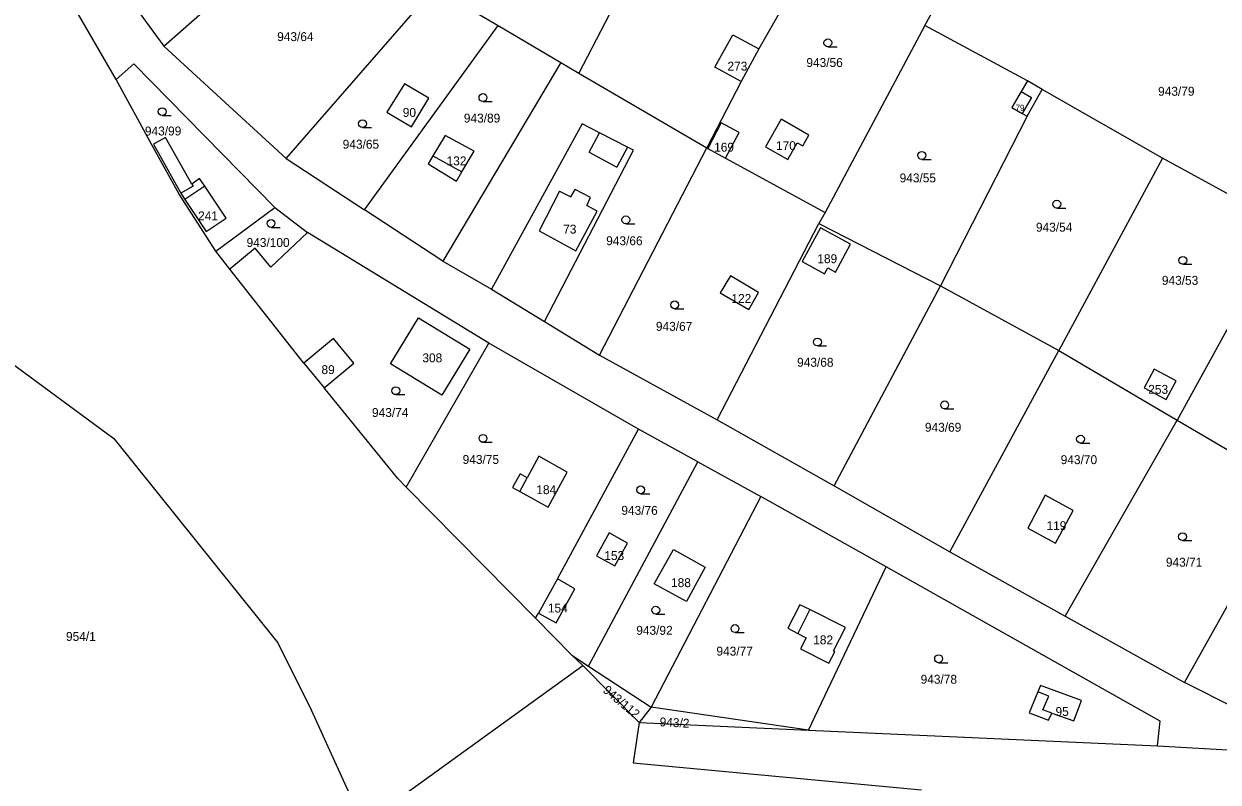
# Model space of a CAD drawing. Extents: x -751333 to -746055, y -1133395 to -1129777.
# Drawn here: x -751034.6 to -750806.6, y -1131231.7 to -1131087 of the extents above; entities that cross this region are included whole.
import ezdxf

# ---------------------------------------------------------------- set-up
doc = ezdxf.new("R2010")
doc.units = 0
for name, color, linetype in [('Hranice parcel', 7, 'Continuous'), ('Parcelní čísla', 7, 'Continuous'), ('Vnitřní kresba', 7, 'Continuous'), ('Značky kultur', 7, 'Continuous')]:
    doc.layers.add(name, color=color, linetype=linetype)

msp = doc.modelspace()

# ---------------------------------------------------------------- linework, layer by layer
at = {"layer": 'Hranice parcel'}
for p, q in [((-751017.03, -1131097.62), (-751052.97, -1131035.02)), ((-750908.02, -1131056.72), (-750928.66, -1131096.41)), ((-751028.03, -1131063.75), (-751007.91, -1131091.26)), ((-751007.91, -1131091.26), (-750978.69, -1131065.52)), ((-750882.26, -1131070.62), (-750894.32, -1131091.73)), ((-750984.53, -1131112.67), (-750956.17, -1131080.13)), ((-750954.6, -1131081.11), (-750944.07, -1131087.29)), ((-750969.58, -1131122.47), (-750944.07, -1131087.29)), ((-750944.07, -1131087.29), (-750932.1, -1131094.36)), ((-750902.67, -1131095.24), (-750899.29, -1131089.06)), ((-750899.29, -1131089.06), (-750894.32, -1131091.73)), ((-750862.62, -1131087.31), (-750881.63, -1131122.97)), ((-750843.03, -1131097.87), (-750862.62, -1131087.31)), ((-751007.91, -1131091.26), (-750984.53, -1131112.67)), ((-750894.32, -1131091.73), (-750897.66, -1131097.98)), ((-750932.1, -1131094.36), (-750954.62, -1131132.27)), ((-750932.1, -1131094.36), (-750928.66, -1131096.41)), ((-750897.66, -1131097.98), (-750902.67, -1131095.24)), ((-750928.66, -1131096.41), (-750904.23, -1131110.65)), ((-750897.66, -1131097.98), (-750904.23, -1131110.65)), ((-750843.03, -1131097.87), (-750844.23, -1131099.89)), ((-750840.17, -1131099.52), (-750843.03, -1131097.87)), ((-750843.07, -1131104.63), (-750840.17, -1131099.52)), ((-750817.2, -1131112.65), (-750840.17, -1131099.52)), ((-750843.07, -1131104.63), (-750859.59, -1131136.99)), ((-750844.01, -1131104.1), (-750843.07, -1131104.63)), ((-750928.04, -1131106.09), (-750945.33, -1131137.63)), ((-750935.22, -1131143.83), (-750918.22, -1131111.09)), ((-750924.73, -1131150.26), (-750904.23, -1131110.65)), ((-750904.23, -1131110.65), (-750904.04, -1131110.76)), ((-750904.04, -1131110.76), (-750900.68, -1131112.63)), ((-750984.53, -1131112.67), (-750969.58, -1131122.47)), ((-750900.68, -1131112.63), (-750881.63, -1131122.97)), ((-750817.2, -1131112.65), (-750837.03, -1131149.34)), ((-750793.96, -1131125.37), (-750817.2, -1131112.65)), ((-750997.95, -1131130.36), (-750986.72, -1131122.03)), ((-750986.72, -1131122.03), (-750980.47, -1131126.84)), ((-750954.62, -1131132.27), (-750969.58, -1131122.47)), ((-750881.63, -1131122.97), (-750882.81, -1131125.12)), ((-750902.26, -1131162.57), (-750882.81, -1131125.12)), ((-750882.81, -1131125.12), (-750859.59, -1131136.99)), ((-750793.96, -1131125.37), (-750814.41, -1131162.65)), ((-750980.47, -1131126.84), (-750987.49, -1131133.44)), ((-750945.82, -1131147.97), (-750980.47, -1131126.84)), ((-750995.3, -1131133.81), (-750997.95, -1131130.36)), ((-750954.62, -1131132.27), (-750945.33, -1131137.63)), ((-750981.17, -1131151.77), (-750995.3, -1131133.81)), ((-750879.9, -1131175.15), (-750859.59, -1131136.99)), ((-750859.59, -1131136.99), (-750837.03, -1131149.34)), ((-750945.33, -1131137.63), (-750935.22, -1131143.83)), ((-750935.22, -1131143.83), (-750924.73, -1131150.26)), ((-750975.52, -1131147.07), (-750981.17, -1131151.77)), ((-750971.63, -1131151.75), (-750975.52, -1131147.07)), ((-750961.63, -1131175.41), (-750945.82, -1131147.97)), ((-750917.27, -1131164.38), (-750945.82, -1131147.97)), ((-750924.73, -1131150.26), (-750902.26, -1131162.57)), ((-750857.83, -1131187.77), (-750837.03, -1131149.34)), ((-750837.03, -1131149.34), (-750814.41, -1131162.65)), ((-750981.17, -1131151.77), (-750977.28, -1131156.45)), ((-750977.28, -1131156.45), (-750971.63, -1131151.75)), ((-750932.76, -1131192.95), (-750917.27, -1131164.38)), ((-750905.93, -1131170.6), (-750917.27, -1131164.38)), ((-750902.26, -1131162.57), (-750879.9, -1131175.15)), ((-750835.82, -1131200.03), (-750814.41, -1131162.65)), ((-750814.41, -1131162.65), (-750792.36, -1131175.65)), ((-750926.84, -1131209.62), (-750905.93, -1131170.6)), ((-750905.93, -1131170.6), (-750893.91, -1131177.18)), ((-750936.94, -1131200.44), (-750961.63, -1131175.41)), ((-750879.9, -1131175.15), (-750857.83, -1131187.77)), ((-750813.01, -1131212.74), (-750792.36, -1131175.65)), ((-750893.91, -1131177.18), (-750914.84, -1131217.45)), ((-750870.01, -1131190.64), (-750893.91, -1131177.18)), ((-750857.83, -1131187.77), (-750835.82, -1131200.03)), ((-750884.83, -1131221.8), (-750870.01, -1131190.64)), ((-750932.76, -1131192.95), (-750936.39, -1131199.46)), ((-750936.94, -1131200.44), (-750936.39, -1131199.46)), ((-750930.01, -1131207.47), (-750936.94, -1131200.44)), ((-750835.82, -1131200.03), (-750813.01, -1131212.74)), ((-750927.92, -1131209.45), (-750930.01, -1131207.47)), ((-750930.01, -1131207.47), (-750926.84, -1131209.62)), ((-750969.82, -1131239.74), (-750927.92, -1131209.45)), ((-750917.14, -1131220.34), (-750927.92, -1131209.45)), ((-750926.84, -1131209.62), (-750914.84, -1131217.45)), ((-750914.84, -1131217.45), (-750917.14, -1131220.34)), ((-750884.83, -1131221.8), (-750914.84, -1131217.45)), ((-750917.14, -1131220.34), (-750884.83, -1131221.8)), ((-750884.83, -1131221.8), (-750818.16, -1131224.81))]:
    msp.add_line(p, q, dxfattribs=at)
for points in [[(-750862.62, -1131087.31), (-750860.26, -1131083.03), (-750882.26, -1131070.62)], [(-751136.31, -1131080.4), (-751119.64, -1131090.87), (-751017.43, -1131166.11), (-750986.12, -1131205.13), (-750979.79, -1131217.93), (-750969.82, -1131239.74)], [(-751017.03, -1131097.62), (-751013.64, -1131094.63), (-750986.72, -1131122.03)], [(-750997.95, -1131130.36), (-751005, -1131119.5), (-751010.19, -1131110.1), (-751017.03, -1131097.62)], [(-750957.32, -1131101.18), (-750961.94, -1131098.45), (-750965.31, -1131103.84), (-750960.59, -1131106.62), (-750957.32, -1131101.18)], [(-750844.23, -1131099.89), (-750845.99, -1131102.97), (-750844.01, -1131104.1)], [(-750888.76, -1131112.87), (-750886.95, -1131109.7), (-750885.91, -1131110.3), (-750884.72, -1131108.21), (-750890.03, -1131105.2), (-750893.01, -1131110.45), (-750888.76, -1131112.87)], [(-750918.22, -1131111.09), (-750919.39, -1131110.51), (-750924.74, -1131107.77), (-750928.04, -1131106.09)], [(-750900.68, -1131112.63), (-750898.07, -1131107.74), (-750901.52, -1131105.87), (-750904.04, -1131110.76)], [(-751002.55, -1131117.59), (-751007.57, -1131108.7), (-751009.88, -1131109.97), (-751004.65, -1131119.29), (-751003.89, -1131120.54), (-750999.79, -1131126.61), (-750995.99, -1131124.05), (-751000.09, -1131117.97), (-751001.08, -1131116.5), (-751002.55, -1131117.59)], [(-750956.54, -1131112.19), (-750957.46, -1131113.73), (-750952.03, -1131116.99), (-750950.98, -1131115.24), (-750948.62, -1131111.3), (-750954.2, -1131108.3), (-750956.54, -1131112.19)], [(-750876.78, -1131129.07), (-750882.5, -1131125.92), (-750886.03, -1131132.33), (-750881.74, -1131134.71), (-750881.11, -1131133.58), (-750879.69, -1131134.36), (-750876.78, -1131129.07)], [(-750987.49, -1131133.44), (-750990.43, -1131129.83), (-750995.3, -1131133.81)], [(-750899.73, -1131135.09), (-750901.68, -1131138.34), (-750896.22, -1131141.51), (-750894.38, -1131138.26), (-750899.73, -1131135.09)], [(-750959.28, -1131143.08), (-750949.46, -1131149.07), (-750954.81, -1131157.86), (-750964.63, -1131151.89), (-750959.28, -1131143.08)], [(-750818.82, -1131152.9), (-750820.71, -1131156.47), (-750816.5, -1131158.69), (-750814.61, -1131155.13), (-750818.82, -1131152.9)], [(-750961.63, -1131175.41), (-750963.24, -1131173.77), (-750977.28, -1131156.45)], [(-750934.54, -1131179.22), (-750930.9, -1131172.57), (-750936.32, -1131169.53), (-750938.5, -1131173.63), (-750939.88, -1131172.88), (-750941.32, -1131175.5), (-750939.94, -1131176.26), (-750934.54, -1131179.22)], [(-750839.6, -1131176.96), (-750842.94, -1131183.25), (-750837.66, -1131186.11), (-750834.29, -1131179.9), (-750839.6, -1131176.96)], [(-750919.35, -1131186.12), (-750922.88, -1131184.16), (-750925.3, -1131188.51), (-750921.77, -1131190.47), (-750919.35, -1131186.12)], [(-750772.25, -1131183.93), (-750792.32, -1131220.74), (-750803.16, -1131217.65), (-750813.01, -1131212.74)], [(-750910.59, -1131187.35), (-750904.54, -1131190.72), (-750906.08, -1131193.48), (-750908.1, -1131197.24), (-750914.25, -1131193.9), (-750913.17, -1131191.98), (-750910.59, -1131187.35)], [(-750818.16, -1131224.81), (-750817.64, -1131220.07), (-750870.01, -1131190.64)], [(-750936.39, -1131199.46), (-750933.02, -1131201.33), (-750929.4, -1131194.82), (-750932.76, -1131192.95)], [(-750879.79, -1131206.83), (-750880.07, -1131206.68), (-750877.77, -1131202.23), (-750884.56, -1131198.77), (-750886.47, -1131197.9), (-750888.79, -1131202.34), (-750886.84, -1131203.37), (-750885.23, -1131204.16), (-750886.32, -1131206.26)], [(-750886.32, -1131206.26), (-750880.93, -1131209.04), (-750879.79, -1131206.83)], [(-750834.16, -1131220.02), (-750832.69, -1131216.13), (-750840.5, -1131213.29), (-750841, -1131214.47), (-750842.7, -1131218.49), (-750838.97, -1131219.91), (-750838.38, -1131218.58), (-750834.16, -1131220.02)], [(-750917.14, -1131220.34), (-750918.27, -1131228.08), (-750863.26, -1131233.19)], [(-750818.16, -1131224.81), (-750709.78, -1131231), (-750659.74, -1131231.2), (-750635.87, -1131230.45)]]:
    msp.add_lwpolyline(points, dxfattribs=at)
at = {"layer": 'Vnitřní kresba'}
for p, q in [((-750844.23, -1131099.89), (-750842.25, -1131101.02)), ((-750842.25, -1131101.02), (-750844.01, -1131104.1)), ((-750926.71, -1131111.49), (-750924.74, -1131107.77)), ((-750956.54, -1131112.19), (-750950.98, -1131115.24)), ((-750926.71, -1131111.49), (-750921.38, -1131114.33)), ((-750919.39, -1131110.51), (-750921.38, -1131114.33)), ((-751002.33, -1131117.98), (-751004.65, -1131119.29)), ((-751000.09, -1131117.97), (-751003.89, -1131120.54)), ((-751002.55, -1131117.59), (-751002.33, -1131117.98)), ((-750932.33, -1131118.91), (-750936.23, -1131126.52)), ((-750932.33, -1131118.91), (-750930.19, -1131120)), ((-750930.19, -1131120), (-750929.39, -1131118.59)), ((-750926.42, -1131120.16), (-750929.39, -1131118.59)), ((-750927.15, -1131121.64), (-750926.42, -1131120.16)), ((-750929.24, -1131130.32), (-750925.17, -1131122.73)), ((-750925.17, -1131122.73), (-750927.15, -1131121.64)), ((-750936.23, -1131126.52), (-750929.24, -1131130.32)), ((-750939.94, -1131176.26), (-750938.5, -1131173.63)), ((-750884.56, -1131198.77), (-750886.84, -1131203.37)), ((-750838.91, -1131215.3), (-750841, -1131214.47)), ((-750840.06, -1131217.92), (-750838.91, -1131215.3)), ((-750838.38, -1131218.58), (-750840.06, -1131217.92))]:
    msp.add_line(p, q, dxfattribs=at)
at = {"layer": 'Značky kultur'}
for p, q in [((-750881.113, -1131091.36), (-750879.363, -1131091.36)), ((-750946.973, -1131101.81), (-750945.223, -1131101.81)), ((-751008.223, -1131104.5), (-751006.473, -1131104.5)), ((-750969.973, -1131106.8), (-750968.223, -1131106.8)), ((-750863.173, -1131112.85), (-750861.423, -1131112.85)), ((-750837.403, -1131122.15), (-750835.653, -1131122.15)), ((-750987.433, -1131125.84), (-750985.683, -1131125.84)), ((-750919.693, -1131125.15), (-750917.943, -1131125.15)), ((-750813.343, -1131132.88), (-750811.593, -1131132.88)), ((-750910.373, -1131141.37), (-750908.623, -1131141.37)), ((-750883.113, -1131148.47), (-750881.363, -1131148.47)), ((-750963.613, -1131157.77), (-750961.863, -1131157.77)), ((-750858.823, -1131160.48), (-750857.073, -1131160.48)), ((-750946.963, -1131166.87), (-750945.213, -1131166.87)), ((-750832.873, -1131167.01), (-750831.123, -1131167.01)), ((-750916.863, -1131176.69), (-750915.113, -1131176.69)), ((-750813.403, -1131185.63), (-750811.653, -1131185.63)), ((-750913.973, -1131199.65), (-750912.223, -1131199.65)), ((-750898.843, -1131203.17), (-750897.093, -1131203.17)), ((-750859.973, -1131208.93), (-750858.223, -1131208.93))]:
    msp.add_line(p, q, dxfattribs=at)
for centre in [(-750881.113, -1131090.61), (-750946.973, -1131101.06), (-751008.223, -1131103.75), (-750969.973, -1131106.05), (-750863.173, -1131112.1), (-750837.403, -1131121.4), (-750919.693, -1131124.4), (-750987.433, -1131125.09), (-750813.343, -1131132.13), (-750910.373, -1131140.62), (-750883.113, -1131147.72), (-750963.613, -1131157.02), (-750858.823, -1131159.73), (-750946.963, -1131166.12), (-750832.873, -1131166.26), (-750916.863, -1131175.94), (-750813.403, -1131184.88), (-750913.973, -1131198.9), (-750898.843, -1131202.42), (-750859.973, -1131208.18)]:
    msp.add_circle(centre, 0.75, dxfattribs=at)

# ---------------------------------------------------------------- texts
at = {"layer": 'Parcelní čísla'}
for s, height, p in [('943/64', 1.7, (-750986.26, -1131090.28)), ('943/56', 1.7, (-750885.22, -1131095.22)), ('273', 1.7, (-750900.28, -1131095.91)), ('943/79', 1.7, (-750818.067, -1131100.71)), ('90', 1.7, (-750962.28, -1131104.75)), ('79', 1.14, (-750845.283, -1131103.57)), ('943/89', 1.7, (-750950.62, -1131105.83)), ('943/99', 1.7, (-751011.517, -1131108.29)), ('943/65', 1.7, (-750973.75, -1131110.82)), ('169', 1.7, (-750902.83, -1131111.38)), ('170', 1.7, (-750891.02, -1131111.09)), ('132', 1.7, (-750953.92, -1131114)), ('943/55', 1.7, (-750867.42, -1131117.25)), ('241', 1.7, (-751001.36, -1131124.48)), ('73', 1.7, (-750931.65, -1131127.02)), ('943/54', 1.7, (-750841.39, -1131126.66)), ('943/100', 1.7, (-750992.1, -1131129.58)), ('943/66', 1.7, (-750923.44, -1131129.24)), ('189', 1.7, (-750883.13, -1131132.67)), ('943/53', 1.7, (-750817.35, -1131136.8)), ('122', 1.7, (-750899.53, -1131140.25)), ('943/67', 1.7, (-750913.95, -1131145.58)), ('308', 1.7, (-750958.535, -1131151.6)), ('943/68', 1.7, (-750886.99, -1131152.44)), ('89', 1.7, (-750977.8, -1131153.84)), ('253', 1.7, (-750819.945, -1131157.61)), ('943/74', 1.7, (-750968.157, -1131162.03)), ('943/69', 1.7, (-750862.59, -1131164.85)), ('943/75', 1.7, (-750950.85, -1131170.99)), ('943/70', 1.7, (-750836.66, -1131171.03)), ('184', 1.7, (-750936.78, -1131176.76)), ('943/76', 1.7, (-750920.55, -1131180.71)), ('119', 1.7, (-750839.37, -1131183.63)), ('153', 1.7, (-750923.8, -1131189.34)), ('943/71', 1.7, (-750816.58, -1131190.6)), ('188', 1.7, (-750911.06, -1131194.51)), ('154', 1.7, (-750934.58, -1131199.35)), ('954/1', 1.7, (-751026.58, -1131204.77)), ('943/92', 1.7, (-750917.7, -1131203.61)), ('943/77', 1.7, (-750902.39, -1131207.58)), ('182', 1.7, (-750883.92, -1131205.43)), ('943/78', 1.7, (-750863.41, -1131212.95)), ('95', 1.7, (-750837.65, -1131219.1))]:
    msp.add_text(s, height=height, dxfattribs=at).set_placement(p)
for s, rotation, p in [('943/112', 320, (-750924.217, -1131214.416)), ('943/2', 357, (-750913.278, -1131221.066))]:
    msp.add_text(s, height=1.7, rotation=rotation, dxfattribs=at).set_placement(p)

doc.saveas('drawing.dxf')
